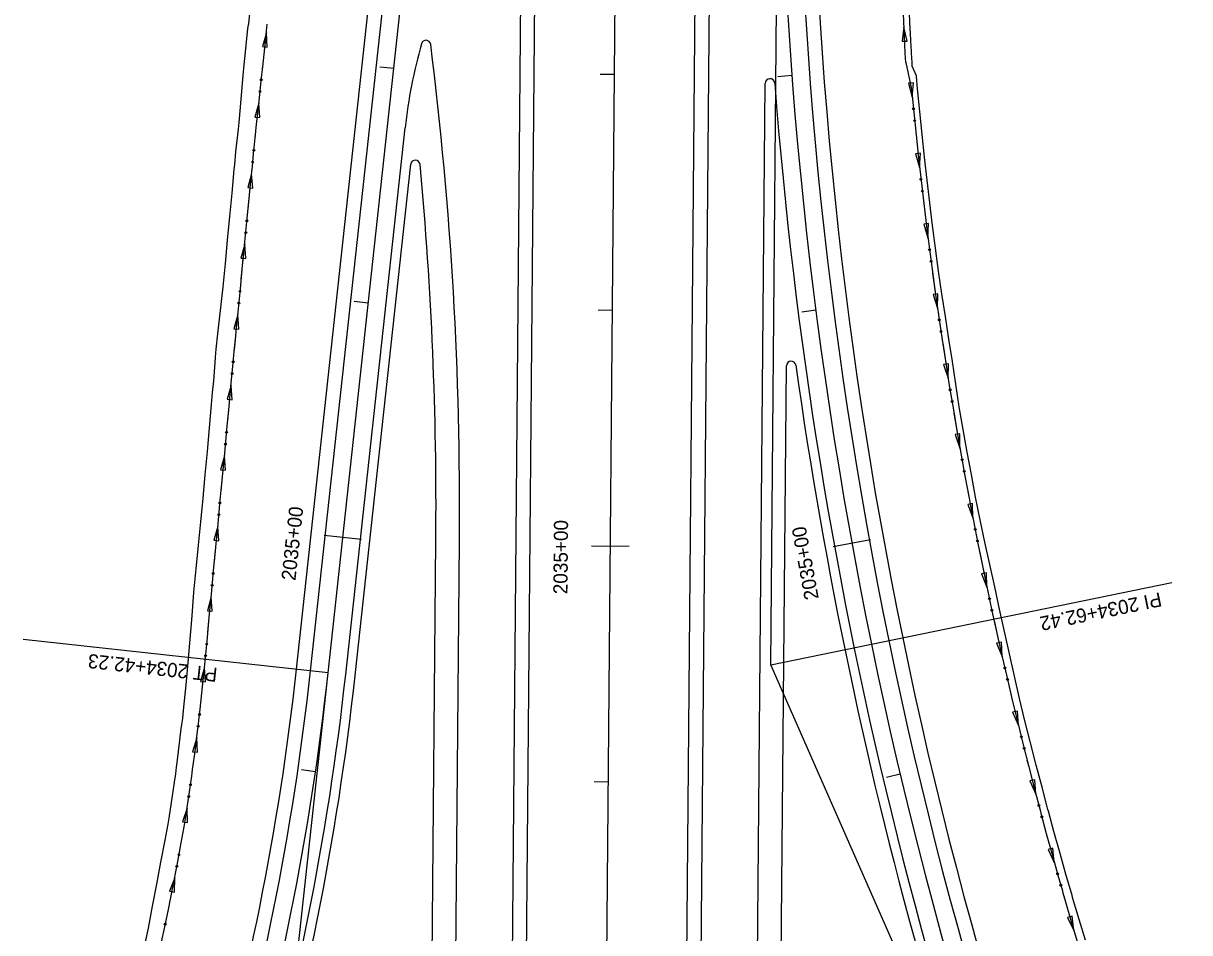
# Model space of a CAD drawing. Extents: x 1611108 to 1749517, y 619561 to 797725.
# Drawn here: x 1713343 to 1713837.5, y 760357.9 to 760743.4 of the extents above; entities that cross this region are included whole.
import ezdxf

# ---------------------------------------------------------------- set-up
doc = ezdxf.new("R2010")
doc.units = 0
for name, color, linetype in [('R_Ditch', 7, 'Continuous'), ('R_Horz Alg', 7, 'Continuous'), ('R_Horz Alg Annot', 7, 'Continuous'), ('R_Horz Alg Stationing', 7, 'Continuous'), ('R_Proposed Const Limits', 7, 'Continuous'), ('R_Proposed Road', 7, 'Continuous'), ('R_Proposed_SHLDR', 7, 'Continuous')]:
    doc.layers.add(name, color=color, linetype=linetype)

msp = doc.modelspace()

# ---------------------------------------------------------------- linework, layer by layer
at = {"layer": 'R_Ditch'}
for p, q in [((1713446.01, 760739.32), (1713444.32, 760733.47)), ((1713446.42, 760733.24), (1713446.01, 760739.32)), ((1713716.4, 760741.78), (1713715.64, 760735.73)), ((1713717.75, 760735.84), (1713716.4, 760741.78)), ((1713715.64, 760735.73), (1713717.75, 760735.84)), ((1713444.32, 760733.47), (1713446.42, 760733.24)), ((1713720.4, 760718.14), (1713718.29, 760717.94)), ((1713718.29, 760717.94), (1713719.92, 760712.07)), ((1713719.92, 760712.07), (1713720.4, 760718.14)), ((1713442.8, 760709.46), (1713441.11, 760703.6)), ((1713443.21, 760703.38), (1713442.8, 760709.46)), ((1713441.11, 760703.6), (1713443.21, 760703.38)), ((1713723.38, 760688.27), (1713721.28, 760688.04)), ((1713721.28, 760688.04), (1713723, 760682.19)), ((1713723, 760682.19), (1713723.38, 760688.27)), ((1713439.76, 760679.57), (1713438.12, 760673.7)), ((1713440.23, 760673.5), (1713439.76, 760679.57)), ((1713438.12, 760673.7), (1713440.23, 760673.5)), ((1713726.85, 760658.45), (1713724.75, 760658.18)), ((1713724.75, 760658.18), (1713726.56, 760652.36)), ((1713726.56, 760652.36), (1713726.85, 760658.45)), ((1713436.84, 760649.68), (1713435.2, 760643.81)), ((1713437.3, 760643.6), (1713436.84, 760649.68)), ((1713435.2, 760643.81), (1713437.3, 760643.6)), ((1713730.8, 760628.69), (1713728.7, 760628.39)), ((1713728.7, 760628.39), (1713730.6, 760622.6)), ((1713730.6, 760622.6), (1713730.8, 760628.69)), ((1713433.91, 760619.78), (1713432.27, 760613.91)), ((1713434.38, 760613.71), (1713433.91, 760619.78)), ((1713432.27, 760613.91), (1713434.38, 760613.71)), ((1713735.23, 760599), (1713733.14, 760598.66)), ((1713733.14, 760598.66), (1713735.13, 760592.91)), ((1713735.13, 760592.91), (1713735.23, 760599)), ((1713431.04, 760589.88), (1713429.42, 760584.01)), ((1713431.53, 760583.81), (1713431.04, 760589.88)), ((1713429.42, 760584.01), (1713431.53, 760583.81)), ((1713740.13, 760569.38), (1713738.05, 760569.01)), ((1713738.05, 760569.01), (1713740.13, 760563.29)), ((1713740.13, 760563.29), (1713740.13, 760569.38)), ((1713428.23, 760559.98), (1713426.61, 760554.1)), ((1713428.72, 760553.9), (1713428.23, 760559.98)), ((1713426.61, 760554.1), (1713428.72, 760553.9)), ((1713745.51, 760539.85), (1713743.43, 760539.44)), ((1713743.43, 760539.44), (1713745.61, 760533.75)), ((1713745.61, 760533.75), (1713745.51, 760539.85)), ((1713425.42, 760530.07), (1713423.8, 760524.19)), ((1713425.91, 760524), (1713425.42, 760530.07)), ((1713423.8, 760524.19), (1713425.91, 760524)), ((1713751.38, 760510.4), (1713749.31, 760509.97)), ((1713749.31, 760509.97), (1713751.57, 760504.31)), ((1713751.57, 760504.31), (1713751.38, 760510.4)), ((1713422.61, 760500.16), (1713420.99, 760494.29)), ((1713423.1, 760494.09), (1713422.61, 760500.16)), ((1713420.99, 760494.29), (1713423.1, 760494.09)), ((1713757.72, 760481.06), (1713755.65, 760480.59)), ((1713755.65, 760480.59), (1713758, 760474.97)), ((1713758, 760474.97), (1713757.72, 760481.06)), ((1713419.79, 760470.26), (1713418.14, 760464.39)), ((1713420.25, 760464.18), (1713419.79, 760470.26)), ((1713418.14, 760464.39), (1713420.25, 760464.18)), ((1713764.53, 760451.82), (1713762.47, 760451.32)), ((1713762.47, 760451.32), (1713764.91, 760445.74)), ((1713764.91, 760445.74), (1713764.53, 760451.82)), ((1713416.49, 760440.4), (1713414.69, 760434.58)), ((1713416.79, 760434.32), (1713416.49, 760440.4)), ((1713414.69, 760434.58), (1713416.79, 760434.32)), ((1713771.81, 760422.7), (1713769.76, 760422.17)), ((1713772.28, 760416.62), (1713771.81, 760422.7)), ((1713769.76, 760422.17), (1713772.28, 760416.62)), ((1713412.37, 760410.65), (1713410.42, 760404.88)), ((1713412.51, 760404.56), (1713412.37, 760410.65)), ((1713410.42, 760404.88), (1713412.51, 760404.56)), ((1713779.54, 760393.69), (1713777.51, 760393.12)), ((1713777.51, 760393.12), (1713780.14, 760387.63)), ((1713780.14, 760387.63), (1713779.54, 760393.69)), ((1713407.14, 760381.07), (1713404.96, 760375.38)), ((1713407.04, 760374.98), (1713407.14, 760381.07)), ((1713404.96, 760375.38), (1713407.04, 760374.98)), ((1713787.77, 760364.82), (1713785.74, 760364.22)), ((1713785.74, 760364.22), (1713788.46, 760358.77)), ((1713788.46, 760358.77), (1713787.77, 760364.82))]:
    msp.add_line(p, q, dxfattribs=at)
for points in [[(1713717.17, 760726.8), (1713716.96, 760730.73), (1713716.77, 760734.4), (1713716.72, 760735.3), (1713716.69, 760735.89), (1713716.67, 760736.33), (1713716.65, 760736.77), (1713716.65, 760736.8), (1713716.57, 760738.35), (1713716.49, 760739.94), (1713716.48, 760740.23), (1713716.47, 760740.35), (1713716.45, 760740.73), (1713716.45, 760740.85), (1713715.99, 760750.74)], [(1713400.46, 760349.06), (1713402.51, 760358.4), (1713404.48, 760367.74), (1713406.37, 760377.11), (1713408.19, 760386.48), (1713409.93, 760395.88), (1713411.14, 760402.68), (1713411.55, 760405.29), (1713413, 760414.73), (1713413.82, 760420.41), (1713413.84, 760420.52), (1713414.36, 760424.19), (1713414.75, 760427.03), (1713415.01, 760428.92), (1713415.64, 760433.65), (1713416.72, 760442.18), (1713416.83, 760443.13), (1713416.87, 760443.42), (1713417.06, 760445.02), (1713417.4, 760447.87), (1713417.95, 760452.61), (1713418.97, 760462.1), (1713419.92, 760471.6), (1713420.85, 760481.45), (1713421.78, 760491.41), (1713422.72, 760501.37), (1713423.66, 760511.32), (1713424.59, 760521.28), (1713425.53, 760531.24), (1713426.46, 760541.2), (1713427.4, 760551.15), (1713428.34, 760561.11), (1713429.27, 760571.07), (1713430.21, 760581.02), (1713430.68, 760586), (1713431.14, 760590.98), (1713432.05, 760600.67), (1713432.08, 760600.94), (1713432.4, 760604.4), (1713433.04, 760610.89), (1713433.41, 760614.69), (1713434.01, 760620.85), (1713434.99, 760630.8), (1713435.96, 760640.75), (1713436.94, 760650.71), (1713437.91, 760660.66), (1713438.88, 760670.61), (1713439.86, 760680.56), (1713440.07, 760682.7), (1713440.6, 760688.11), (1713440.83, 760690.52), (1713441.54, 760697.71), (1713441.54, 760697.72), (1713441.83, 760700.47), (1713442.9, 760710.41), (1713443.97, 760720.35), (1713444.47, 760724.96), (1713445.04, 760730.3), (1713446.11, 760740.24), (1713446.4, 760742.94), (1713446.41, 760743.01)], [(1713444.41, 760724.41), (1713444.47, 760724.96), (1713445.04, 760730.3), (1713446.01, 760739.32)], [(1713717.17, 760726.8), (1713716.96, 760730.73), (1713716.77, 760734.4), (1713716.72, 760735.3), (1713716.69, 760735.89), (1713716.67, 760736.33), (1713716.65, 760736.77), (1713716.65, 760736.8), (1713716.57, 760738.35), (1713716.49, 760739.94), (1713716.48, 760740.23), (1713716.47, 760740.35), (1713716.45, 760740.73), (1713716.45, 760740.85), (1713716.4, 760741.78)], [(1713444.4, 760724.37), (1713444.41, 760724.41)], [(1713717.17, 760726.8), (1713719.6, 760715.4), (1713720.53, 760705.7), (1713721.51, 760696.02), (1713722.54, 760686.33), (1713723.62, 760676.66), (1713724.75, 760666.99), (1713725.93, 760657.33), (1713727.16, 760647.67), (1713728.44, 760638.02), (1713729.77, 760628.38), (1713731.16, 760618.75), (1713732.59, 760609.12), (1713734.07, 760599.5), (1713735.61, 760589.89), (1713737.19, 760580.29), (1713738.83, 760570.7), (1713740.51, 760561.12), (1713742.24, 760551.55), (1713744.03, 760541.99), (1713744.94, 760537.21), (1713745.86, 760532.44), (1713747.75, 760522.89), (1713749.68, 760513.36), (1713751.67, 760503.84), (1713753.7, 760494.33), (1713755.78, 760484.84), (1713757.91, 760475.35), (1713760.1, 760465.88), (1713762.32, 760456.44), (1713762.33, 760456.41), (1713764.61, 760446.96), (1713766.94, 760437.53), (1713769.32, 760428.1), (1713771.75, 760418.69), (1713773.94, 760410.37), (1713774.23, 760409.3), (1713774.44, 760408.51), (1713776.75, 760399.91), (1713779.33, 760390.54), (1713781.95, 760381.19), (1713782.98, 760377.57), (1713783.02, 760377.45), (1713783.28, 760376.52), (1713783.55, 760375.58), (1713783.82, 760374.65), (1713784.09, 760373.71), (1713784.36, 760372.78), (1713784.63, 760371.85), (1713787.35, 760362.52), (1713789.98, 760353.68)], [(1713717.17, 760726.8), (1713719.6, 760715.4), (1713719.92, 760712.07)], [(1713441.23, 760694.54), (1713441.54, 760697.71), (1713441.54, 760697.72), (1713441.83, 760700.47), (1713442.8, 760709.46)], [(1713441.22, 760694.5), (1713441.23, 760694.54)], [(1713721.39, 760697.14), (1713721.4, 760697.11)], [(1713721.4, 760697.1), (1713721.51, 760696.02), (1713722.54, 760686.33), (1713723, 760682.19)], [(1713438.3, 760664.64), (1713438.88, 760670.61), (1713439.76, 760679.57)], [(1713438.3, 760664.61), (1713438.3, 760664.64)], [(1713724.71, 760667.29), (1713724.72, 760667.25)], [(1713724.72, 760667.25), (1713724.75, 760666.99), (1713725.93, 760657.33), (1713726.56, 760652.36)], [(1713435.37, 760634.75), (1713435.96, 760640.75), (1713436.84, 760649.68)], [(1713728.51, 760637.49), (1713728.52, 760637.46)], [(1713728.52, 760637.46), (1713729.77, 760628.38), (1713730.6, 760622.6)], [(1713435.37, 760634.71), (1713435.37, 760634.75)], [(1713432.45, 760604.85), (1713433.04, 760610.89), (1713433.41, 760614.69), (1713433.91, 760619.78)], [(1713732.8, 760607.76), (1713732.81, 760607.73)], [(1713732.81, 760607.72), (1713734.07, 760599.5), (1713735.13, 760592.91)], [(1713432.45, 760604.82), (1713432.45, 760604.85)], [(1713429.64, 760574.95), (1713430.21, 760581.02), (1713430.68, 760586), (1713431.04, 760589.88)], [(1713737.57, 760578.11), (1713737.57, 760578.07)], [(1713737.57, 760578.07), (1713738.83, 760570.7), (1713740.13, 760563.29)], [(1713429.63, 760574.91), (1713429.64, 760574.95)], [(1713426.83, 760545.04), (1713427.4, 760551.15), (1713428.23, 760559.98)], [(1713742.81, 760548.53), (1713742.82, 760548.49)], [(1713742.82, 760548.49), (1713744.03, 760541.99), (1713744.94, 760537.21), (1713745.61, 760533.75)], [(1713426.82, 760545), (1713426.83, 760545.04)], [(1713424.01, 760515.14), (1713424.59, 760521.28), (1713425.42, 760530.07)], [(1713748.53, 760519.04), (1713748.54, 760519)], [(1713748.54, 760519), (1713749.68, 760513.36), (1713751.57, 760504.31)], [(1713424.01, 760515.1), (1713424.01, 760515.13)], [(1713421.2, 760485.23), (1713421.78, 760491.41), (1713422.61, 760500.16)], [(1713754.73, 760489.65), (1713754.73, 760489.61)], [(1713754.73, 760489.61), (1713755.78, 760484.84), (1713757.91, 760475.35), (1713758, 760474.97)], [(1713421.2, 760485.19), (1713421.2, 760485.23)], [(1713418.24, 760455.34), (1713418.97, 760462.1), (1713419.79, 760470.26)], [(1713761.4, 760460.36), (1713761.41, 760460.33)], [(1713761.41, 760460.33), (1713762.32, 760456.44), (1713762.33, 760456.41), (1713764.61, 760446.96), (1713764.91, 760445.74)], [(1713418.24, 760455.3), (1713418.24, 760455.34)], [(1713414.54, 760425.53), (1713414.75, 760427.03), (1713415.01, 760428.92), (1713415.64, 760433.65), (1713416.49, 760440.4)], [(1713768.54, 760431.19), (1713768.55, 760431.15)], [(1713768.55, 760431.15), (1713769.32, 760428.1), (1713771.75, 760418.69), (1713772.29, 760416.62)], [(1713414.54, 760425.49), (1713414.54, 760425.53)], [(1713409.93, 760395.85), (1713409.93, 760395.88), (1713411.14, 760402.68), (1713411.55, 760405.29), (1713412.37, 760410.65)], [(1713776.15, 760402.13), (1713776.16, 760402.09)], [(1713776.16, 760402.09), (1713776.75, 760399.91), (1713779.33, 760390.54), (1713780.14, 760387.63)], [(1713409.92, 760395.81), (1713409.93, 760395.85)], [(1713404.19, 760366.37), (1713404.48, 760367.74), (1713406.37, 760377.11), (1713407.14, 760381.07)], [(1713784.24, 760373.2), (1713784.25, 760373.16)], [(1713784.25, 760373.16), (1713784.36, 760372.78), (1713784.63, 760371.85), (1713787.35, 760362.52), (1713788.46, 760358.77)], [(1713404.18, 760366.33), (1713404.19, 760366.37)]]:
    msp.add_lwpolyline(points, dxfattribs=at)
for centre in [(1713443.84, 760719.42), (1713443.3, 760714.44), (1713720.43, 760707.09), (1713720.93, 760702.11), (1713440.7, 760689.54), (1713440.21, 760684.56), (1713723.59, 760677.22), (1713724.17, 760672.24), (1713437.78, 760659.65), (1713437.29, 760654.66), (1713727.23, 760647.4), (1713727.89, 760642.44), (1713434.85, 760629.75), (1713434.36, 760624.77), (1713731.36, 760617.65), (1713732.09, 760612.7), (1713431.94, 760599.86), (1713431.47, 760594.87), (1713735.96, 760587.97), (1713736.78, 760583.03), (1713429.13, 760569.95), (1713428.66, 760564.96), (1713741.05, 760558.37), (1713741.94, 760553.44), (1713426.32, 760540.04), (1713425.85, 760535.06), (1713746.61, 760528.85), (1713747.58, 760523.93), (1713423.51, 760510.14), (1713423.04, 760505.15), (1713752.65, 760499.42), (1713753.69, 760494.53), (1713420.7, 760480.23), (1713420.23, 760475.24), (1713759.16, 760470.1), (1713760.29, 760465.22), (1713417.65, 760450.35), (1713417.07, 760445.37), (1713766.15, 760440.89), (1713767.36, 760436.03), (1713413.81, 760420.56), (1713413.09, 760415.6), (1713773.6, 760411.79), (1713774.89, 760406.95), (1713408.98, 760390.92), (1713408.06, 760385.99), (1713781.53, 760382.82), (1713782.9, 760378), (1713403.12, 760361.46)]:
    msp.add_circle(centre, 0.375, dxfattribs=at)
at = {"layer": 'R_Horz Alg'}
for p, q in [((1713561.33, 757021.94), (1713607.03, 762259.43)), ((1713472.2, 760468.05), (1713530.07, 761000.06))]:
    msp.add_line(p, q, dxfattribs=at)
for centre, radius, start, end in [((1715573.3, 760864.98), 1909.86, 179.5, 203.75), ((1712333, 760591.97), 1145.92, 333.16667, 353.79167)]:
    msp.add_arc(centre, radius, start, end, dxfattribs=at)
at = {"layer": 'R_Horz Alg Annot'}
for points in [[(1713825.18, 760095.79), (1713659.93, 760471.35), (1713663.51, 760881.65)], [(1713659.93, 760471.35), (1713829.95, 760506.33)], [(1713472.2, 760468.05), (1713342.96, 760482.11)], [(1713355.53, 760074.71), (1713449.65, 760260.77), (1713472.2, 760468.05)]]:
    msp.add_lwpolyline(points, dxfattribs=at)
at = {"layer": 'R_Horz Alg Stationing'}
for points in [[(1713494.11, 760724.96), (1713500.07, 760724.31)], [(1713587.61, 760721.85), (1713593.61, 760721.8)], [(1713662.86, 760720.88), (1713668.85, 760721.33)], [(1713483.29, 760625.54), (1713489.26, 760624.9)], [(1713586.74, 760621.86), (1713592.74, 760621.81)], [(1713673.02, 760621.1), (1713678.98, 760621.86)], [(1713470.49, 760526.35), (1713486.4, 760524.62)], [(1713583.87, 760521.88), (1713599.87, 760521.74)], [(1713686.42, 760521.62), (1713702.17, 760524.48)], [(1713460.92, 760427.03), (1713466.86, 760426.16)], [(1713708.93, 760423.8), (1713714.77, 760425.18)], [(1713585, 760421.87), (1713591, 760421.81)]]:
    msp.add_lwpolyline(points, dxfattribs=at)
at = {"layer": 'R_Proposed Const Limits'}
for points in [[(1713438.48, 760742.66), (1713438.53, 760743.16), (1713439.56, 760753.15)], [(1713719.9, 760725.16), (1713719.81, 760726.78), (1713719.59, 760730.7), (1713719.39, 760734.38), (1713719.34, 760735.28), (1713719.31, 760735.86), (1713719.29, 760736.31), (1713719.26, 760736.75), (1713719.26, 760736.78), (1713719.18, 760738.33), (1713719.1, 760739.92), (1713719.08, 760740.21), (1713719.08, 760740.33), (1713719.06, 760740.71), (1713719.05, 760740.83), (1713718.64, 760750.71)], [(1713393.99, 760350.54), (1713395.99, 760359.82), (1713397.74, 760369.15), (1713399.52, 760378.48), (1713401.33, 760387.8), (1713403.09, 760397.12), (1713404.43, 760403.86), (1713404.84, 760406.45), (1713406.26, 760415.84), (1713407.07, 760421.48), (1713407.09, 760421.59), (1713407.59, 760425.24), (1713407.95, 760428.06), (1713408.18, 760429.95), (1713408.76, 760434.66), (1713409.74, 760443.14), (1713409.88, 760444.08), (1713409.92, 760444.37), (1713410.15, 760445.96), (1713410.53, 760448.78), (1713411.03, 760453.5), (1713411.97, 760462.94), (1713412.84, 760472.38), (1713413.68, 760482.23), (1713414.54, 760492.2), (1713415.33, 760502.17), (1713416.26, 760512.13), (1713417.25, 760522.08), (1713418.23, 760532.03), (1713419.16, 760541.99), (1713420.09, 760551.95), (1713421.02, 760561.91), (1713421.95, 760571.86), (1713422.81, 760581.83), (1713423.22, 760586.81), (1713423.69, 760591.79), (1713424.43, 760601.5), (1713424.45, 760601.77), (1713424.72, 760605.24), (1713425.45, 760611.72), (1713425.91, 760615.51), (1713426.59, 760621.65), (1713427.65, 760631.6), (1713428.67, 760641.54), (1713429.6, 760651.5), (1713430.53, 760661.46), (1713431.45, 760671.42), (1713432.38, 760681.38), (1713432.58, 760683.51), (1713433.13, 760688.93), (1713433.39, 760691.33), (1713434.16, 760698.52), (1713434.16, 760698.53), (1713434.42, 760701.27), (1713435.3, 760711.24), (1713436.18, 760721.2), (1713436.58, 760725.82), (1713437.11, 760731.16), (1713438.21, 760741.1), (1713438.48, 760742.66)], [(1713793.34, 760354.64), (1713790.68, 760363.46), (1713787.92, 760372.75), (1713787.65, 760373.69), (1713787.37, 760374.62), (1713787.09, 760375.54), (1713786.82, 760376.48), (1713786.55, 760377.41), (1713786.28, 760378.34), (1713786.25, 760378.46), (1713785.21, 760382.07), (1713782.56, 760391.4), (1713779.97, 760400.74), (1713777.64, 760409.32), (1713777.42, 760410.11), (1713777.14, 760411.18), (1713774.93, 760419.48), (1713772.48, 760428.87), (1713770.08, 760438.27), (1713767.69, 760447.68), (1713765.37, 760457.1), (1713765.36, 760457.12), (1713763.21, 760466.56), (1713761.07, 760476.03), (1713758.96, 760485.5), (1713756.91, 760494.99), (1713754.9, 760504.48), (1713752.77, 760513.96), (1713750.69, 760523.45), (1713748.66, 760532.94), (1713747.7, 760537.71), (1713746.78, 760542.47), (1713744.97, 760552.02), (1713743.21, 760561.57), (1713741.49, 760571.13), (1713739.84, 760580.71), (1713738.44, 760590.32), (1713737.02, 760599.93), (1713735.47, 760609.52), (1713733.99, 760619.12), (1713732.5, 760628.73), (1713731.1, 760638.35), (1713729.81, 760647.98), (1713728.51, 760657.62), (1713727.32, 760667.26), (1713726.19, 760676.92), (1713725.11, 760686.58), (1713724.06, 760696.25), (1713723.07, 760705.92), (1713722.13, 760715.6), (1713721.64, 760720.91), (1713721.65, 760721.09), (1713719.9, 760725.16)]]:
    msp.add_lwpolyline(points, dxfattribs=at)
at = {"layer": 'R_Proposed Road'}
for p, q in [((1713541.83, 759372.2), (1713567.03, 762259.78)), ((1713547.83, 759372.15), (1713573.03, 762259.72)), ((1713615.83, 759371.56), (1713641.03, 762259.13)), ((1713621.83, 759371.5), (1713647.03, 762259.08)), ((1713464.74, 760468.86), (1713522.61, 761000.87)), ((1713645.83, 759371.3), (1713657.58, 760717.92)), ((1713479.65, 760467.24), (1713504.87, 760699.09)), ((1713655.83, 759371.21), (1713666.54, 760598.16)), ((1713507.84, 759372.5), (1713517.89, 760524.26)), ((1713517.83, 759372.41), (1713527.89, 760524.17))]:
    msp.add_line(p, q, dxfattribs=at)
for centre, radius, start, end in [((1715573.3, 760864.98), 1902.36, 179.5, 203.75), ((1713721.1, 760675.57), 217.5, 164.2202, 173.7917), ((1713513.72, 760734.17), 2, 7.133, 164.2202), ((1711945.95, 760537.98), 1582, 359.5, 7.13298), ((1713659.58, 760717.9), 2, 4.3949, 179.5), ((1715573.3, 760864.98), 1917.36, 184.39486, 203.75), ((1712333, 760591.97), 1138.42, 333.16667, 353.79167), ((1712333, 760591.97), 1153.42, 333.16667, 353.79167)]:
    msp.add_arc(centre, radius, start, end, dxfattribs=at)
at = {"layer": 'R_Proposed_SHLDR'}
for p, q in [((1713458.77, 760469.51), (1713516.65, 761001.52)), ((1713483.63, 760466.81), (1713507.21, 760683.6))]:
    msp.add_line(p, q, dxfattribs=at)
for centre, radius, start, end in [((1715573.3, 760864.98), 1896.36, 179.5, 203.75), ((1713509.2, 760683.38), 2, 5.3139, 173.7917), ((1711945.95, 760537.98), 1572, 359.5, 5.31392), ((1713668.54, 760598.15), 2, 7.9745, 179.5), ((1715573.3, 760864.98), 1921.36, 187.97448, 203.75), ((1712333, 760591.97), 1132.42, 333.16667, 353.79167), ((1712333, 760591.97), 1157.42, 333.16667, 353.79167)]:
    msp.add_arc(centre, radius, start, end, dxfattribs=at)

# ---------------------------------------------------------------- texts
at = {"layer": 'R_Horz Alg Annot'}
for s, rotation, p in [('PI 2034+62.42', 191.625, (1713824.95, 760502.22)), ('PT 2034+42.23', 173.7917, (1713425.52, 760470.11))]:
    msp.add_text(s, height=6, rotation=rotation, dxfattribs=at).set_placement(p)
at = {"layer": 'R_Horz Alg Stationing'}
for rotation, p in [(83.7917, (1713458.32, 760506.9)), (89.5, (1713573.69, 760501.32)), (100.3134, (1713680.28, 760499.52))]:
    msp.add_text('2035+00', height=6, rotation=rotation, dxfattribs=at).set_placement(p)

doc.saveas('drawing.dxf')
